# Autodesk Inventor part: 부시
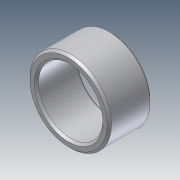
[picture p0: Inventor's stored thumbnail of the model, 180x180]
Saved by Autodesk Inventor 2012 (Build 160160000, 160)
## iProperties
Company: 한국ATC센터
Created: 2013-01
Part Number: 부시
Document SubType Name: Modeling
Designer: KYOUNG IL JANG
Density: 1 g/cm^3
Material: 기본값
Author: KYOUNG IL JANG
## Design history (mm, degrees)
sketch "스케치1"
  geometry: L1 (15, 20)-(15, -46) reference; L2 (-20, 19)-(20, 19); L3 (30.7, -1)-(-30.7, -1) reference; L4 (19, 19)-(19, -1); L5 (15, -1)-(19, -1); L6 (0, 0)-(0, 19); L7 (19, 19)-(15, 19)
  constraints: 12 end point, 6 point on line, 1 collinear, 1 midpoint, 1 perpendicular, 1 vertical, 2 other
  dimensions: "d0" = 38 diameter of L4 L6; "d5" = 20 distance between parallel lines of L2 L3
revolve "회전1" sketch "스케치1" stored, may be unused: angle "d1" = 90 deg
chamfer "모따기1" distance "d2" = 1; stored, may be unused: second distance "d3" = 2, angle "d4" = 45 deg
node "솔리드1"
node "참조2"
